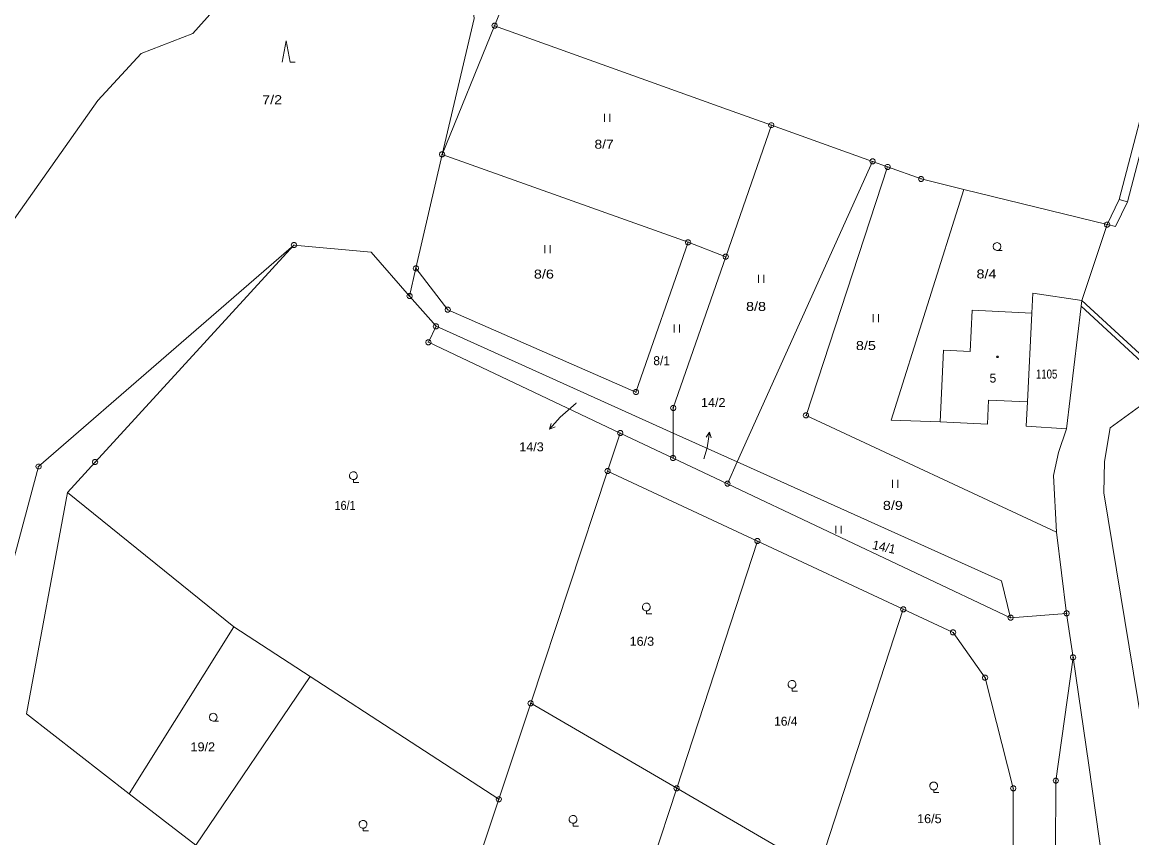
# Model space of a CAD drawing. Extents: x -687390 to -684106, y -954833 to -951648.
# Drawn here: x -686842.5 to -686632.4, y -952252.9 to -952098.4 of the extents above; entities that cross this region are included whole.
import ezdxf
from ezdxf.enums import TextEntityAlignment as Align

# ---------------------------------------------------------------- set-up
doc = ezdxf.new("R2010")
doc.units = 0
doc.header["$LTSCALE"] = 0.68
for name, color, linetype, lineweight in [('1', 7, 'Continuous', 13), ('3', 7, 'Continuous', 13), ('4', 7, 'Continuous', 13), ('5', 7, 'Continuous', 13), ('7', 7, 'Continuous', 13), ('8', 7, 'Continuous', 13)]:
    doc.layers.add(name, color=color, linetype=linetype, lineweight=lineweight)
doc.layers.add('2', color=7, linetype='Continuous')

msp = doc.modelspace()

# ---------------------------------------------------------------- linework, layer by layer
at = {"layer": '1'}
for p, q in [((-686753.07, -952099.08), (-686722.93, -952025.33)), ((-686624.07, -952090.85), (-686634.75, -952131.94)), ((-686753.07, -952099.08), (-686708.93, -952114.92)), ((-686678.63, -952125.8), (-686681.47, -952124.77)), ((-686678.63, -952125.8), (-686672.27, -952128.08)), ((-686672.27, -952128.08), (-686664.21, -952130.05)), ((-686664.21, -952130.05), (-686637.06, -952136.72)), ((-686637.06, -952136.72), (-686634.75, -952131.94)), ((-686641.87, -952151.11), (-686637.06, -952136.72)), ((-686791.07, -952140.62), (-686828.73, -952181.72)), ((-686767.96, -952145), (-686769.17, -952150.27)), ((-686769.17, -952150.27), (-686764.16, -952155.98)), ((-686662.64, -952152.96), (-686662.99, -952160.75)), ((-686651.34, -952153.47), (-686662.64, -952152.96)), ((-686651.34, -952153.47), (-686652.15, -952170.29)), ((-686729.26, -952176.22), (-686765.61, -952159.02)), ((-686668.65, -952174.1), (-686668.04, -952160.52)), ((-686662.99, -952160.75), (-686668.04, -952160.52)), ((-686659.51, -952169.96), (-686659.71, -952174.51)), ((-686652.15, -952170.29), (-686659.51, -952169.96)), ((-686652.15, -952170.29), (-686652.36, -952174.88)), ((-686659.71, -952174.51), (-686668.65, -952174.1)), ((-686644.75, -952175.43), (-686652.36, -952174.88)), ((-686719.24, -952176.21), (-686707.09, -952181.68)), ((-686833.98, -952187.46), (-686828.73, -952181.72)), ((-686657.05, -952204.22), (-686707.09, -952181.68)), ((-686647.2, -952184.25), (-686646.63, -952194.98)), ((-686841.73, -952229.38), (-686833.98, -952187.46)), ((-686703.29, -952196.66), (-686718.58, -952243.49)), ((-686646.63, -952194.98), (-686644.72, -952210.37)), ((-686675.65, -952209.59), (-686691.8, -952259.08)), ((-686655.32, -952211.18), (-686644.72, -952210.37)), ((-686644.72, -952210.37), (-686643.5, -952218.69)), ((-686643.5, -952218.69), (-686646.76, -952242.06)), ((-686643.5, -952218.69), (-686640.5, -952239.1)), ((-686752.26, -952245.56), (-686746.23, -952227.39)), ((-686635.56, -952274.27), (-686640.5, -952239.1)), ((-686718.58, -952243.49), (-686730.67, -952280.52))]:
    msp.add_line(p, q, dxfattribs=at)
for points in [[(-686704.5, -951972.19), (-686761.7, -952058.6), (-686756.92, -952097.72), (-686763.02, -952123.44)], [(-686798.99, -952084.75), (-686803.69, -952093.23), (-686810.2, -952100.56), (-686819.98, -952104.32), (-686828.22, -952113.25), (-686872.69, -952176.15), (-686879.03, -952189.6)], [(-686753.07, -952099.08), (-686763.02, -952123.44), (-686767.96, -952145)], [(-686681.47, -952124.77), (-686700.65, -952117.9), (-686708.93, -952114.92)], [(-686700.65, -952117.9), (-686709.29, -952142.81), (-686716.42, -952140.08), (-686763.02, -952123.44)], [(-686708.95, -952185.82), (-686707.09, -952181.68), (-686681.47, -952124.77)], [(-686678.63, -952125.8), (-686694.08, -952172.88), (-686646.63, -952194.98)], [(-686668.65, -952174.1), (-686677.96, -952173.76), (-686664.21, -952130.05)], [(-686791.07, -952140.62), (-686839.43, -952182.55), (-686849.46, -952219.82), (-686861.27, -952225.02), (-686852.17, -952273.36), (-686866.54, -952281.02)], [(-686769.17, -952150.27), (-686776.45, -952141.95), (-686791.07, -952140.62)], [(-686716.42, -952140.08), (-686726.3, -952168.45), (-686761.94, -952152.86), (-686767.96, -952145)], [(-686709.29, -952142.81), (-686719.22, -952171.46), (-686719.24, -952176.21), (-686719.25, -952180.95)], [(-686651.34, -952153.47), (-686651.09, -952149.69), (-686641.87, -952151.11), (-686641.99, -952152.16)], [(-686623.24, -952169.45), (-686641.99, -952152.16), (-686644.75, -952175.43)], [(-686765.61, -952159.02), (-686764.16, -952155.98), (-686719.24, -952176.21)], [(-686627.26, -952250.86), (-686637.68, -952187.53), (-686637.52, -952181.59), (-686636.46, -952175.22), (-686628.12, -952169.13), (-686623.24, -952169.45)], [(-686644.75, -952175.43), (-686646.26, -952179.91), (-686647.2, -952184.25)], [(-686746.23, -952227.39), (-686731.65, -952183.41), (-686729.26, -952176.22)], [(-686708.95, -952185.82), (-686719.25, -952180.95), (-686729.26, -952176.22)], [(-686731.65, -952183.41), (-686703.29, -952196.66), (-686675.65, -952209.59), (-686666.23, -952213.98), (-686660.17, -952222.54), (-686654.82, -952243.48), (-686654.84, -952268.78), (-686665.05, -952274.64), (-686691.8, -952259.08), (-686718.58, -952243.49), (-686746.23, -952227.39)], [(-686657.05, -952204.22), (-686655.32, -952211.18), (-686708.95, -952185.82)], [(-686841.73, -952229.38), (-686822.25, -952244.56), (-686802.48, -952212.91), (-686788.01, -952222.33)], [(-686822.25, -952244.56), (-686809.68, -952254.23), (-686788.01, -952222.33)], [(-686757.85, -952262.42), (-686752.26, -952245.56), (-686788.01, -952222.33)], [(-686646.76, -952242.06), (-686646.86, -952269.57), (-686655.44, -952300.69)]]:
    msp.add_lwpolyline(points, dxfattribs=at)
at = {"layer": '3'}
for p, q in [((-686732.26, -952115.74), (-686732.26, -952117.24)), ((-686731.26, -952117.24), (-686731.26, -952115.74)), ((-686743.57, -952140.61), (-686743.57, -952142.11)), ((-686742.57, -952142.11), (-686742.57, -952140.61)), ((-686703.05, -952146.26), (-686703.05, -952147.76)), ((-686702.05, -952147.76), (-686702.05, -952146.26)), ((-686681.35, -952153.7), (-686681.35, -952155.2)), ((-686680.35, -952155.2), (-686680.35, -952153.7)), ((-686719.03, -952155.67), (-686719.03, -952157.17)), ((-686718.03, -952157.17), (-686718.03, -952155.67)), ((-686677.69, -952185.07), (-686677.69, -952186.57)), ((-686676.69, -952186.57), (-686676.69, -952185.07)), ((-686688.43, -952193.75), (-686688.43, -952195.25)), ((-686687.43, -952195.25), (-686687.43, -952193.75))]:
    msp.add_line(p, q, dxfattribs=at)
for points in [[(-686793.31, -952105.93), (-686792.56, -952101.93), (-686791.81, -952105.93), (-686790.81, -952105.93)], [(-686657.89, -952141.62), (-686658.27, -952141.52), (-686658.54, -952141.25), (-686658.64, -952140.88), (-686658.54, -952140.51), (-686658.27, -952140.24), (-686657.9, -952140.14), (-686657.53, -952140.24), (-686657.26, -952140.51), (-686657.16, -952140.89), (-686657.26, -952141.27), (-686657.53, -952141.54), (-686657.91, -952141.64), (-686656.91, -952141.64)], [(-686779.81, -952185.01), (-686780, -952185.01), (-686780.34, -952184.82), (-686780.53, -952184.48), (-686780.53, -952184.09), (-686780.34, -952183.75), (-686780, -952183.56), (-686779.61, -952183.56), (-686779.27, -952183.75), (-686779.08, -952184.09), (-686779.08, -952184.48), (-686779.27, -952184.82), (-686779.61, -952185.01), (-686779.8, -952185.01), (-686779.8, -952185.54), (-686778.8, -952185.54)], [(-686724.32, -952209.9), (-686724.51, -952209.9), (-686724.85, -952209.71), (-686725.04, -952209.37), (-686725.04, -952208.98), (-686724.85, -952208.64), (-686724.51, -952208.45), (-686724.12, -952208.45), (-686723.78, -952208.64), (-686723.59, -952208.98), (-686723.59, -952209.37), (-686723.78, -952209.71), (-686724.12, -952209.9), (-686724.31, -952209.9), (-686724.31, -952210.43), (-686723.31, -952210.43)], [(-686696.72, -952224.55), (-686696.91, -952224.55), (-686697.25, -952224.36), (-686697.44, -952224.02), (-686697.44, -952223.63), (-686697.25, -952223.29), (-686696.91, -952223.1), (-686696.52, -952223.1), (-686696.18, -952223.29), (-686695.99, -952223.63), (-686695.99, -952224.02), (-686696.18, -952224.36), (-686696.52, -952224.55), (-686696.71, -952224.55), (-686696.71, -952225.08), (-686695.71, -952225.08)], [(-686806.34, -952230.76), (-686806.72, -952230.66), (-686806.99, -952230.39), (-686807.09, -952230.02), (-686806.99, -952229.65), (-686806.72, -952229.38), (-686806.35, -952229.28), (-686805.98, -952229.38), (-686805.71, -952229.65), (-686805.61, -952230.03), (-686805.71, -952230.41), (-686805.98, -952230.68), (-686806.36, -952230.78), (-686805.36, -952230.78)], [(-686669.91, -952243.76), (-686670.1, -952243.76), (-686670.44, -952243.57), (-686670.63, -952243.23), (-686670.63, -952242.84), (-686670.44, -952242.5), (-686670.1, -952242.31), (-686669.71, -952242.31), (-686669.37, -952242.5), (-686669.18, -952242.84), (-686669.18, -952243.23), (-686669.37, -952243.57), (-686669.71, -952243.76), (-686669.9, -952243.76), (-686669.9, -952244.29), (-686668.9, -952244.29)], [(-686738.2, -952250.1), (-686738.39, -952250.1), (-686738.73, -952249.91), (-686738.92, -952249.57), (-686738.92, -952249.18), (-686738.73, -952248.84), (-686738.39, -952248.65), (-686738, -952248.65), (-686737.66, -952248.84), (-686737.47, -952249.18), (-686737.47, -952249.57), (-686737.66, -952249.91), (-686738, -952250.1), (-686738.19, -952250.1), (-686738.19, -952250.63), (-686737.19, -952250.63)], [(-686777.98, -952251.01), (-686778.17, -952251.01), (-686778.51, -952250.82), (-686778.7, -952250.48), (-686778.7, -952250.09), (-686778.51, -952249.75), (-686778.17, -952249.56), (-686777.78, -952249.56), (-686777.44, -952249.75), (-686777.25, -952250.09), (-686777.25, -952250.48), (-686777.44, -952250.82), (-686777.78, -952251.01), (-686777.97, -952251.01), (-686777.97, -952251.54), (-686776.97, -952251.54)]]:
    msp.add_lwpolyline(points, dxfattribs=at)
at = {"layer": '4'}
for p, q in [((-686635.49, -952137.11), (-686633.22, -952132.4)), ((-686635.49, -952137.11), (-686637.06, -952136.72)), ((-686641.87, -952151.11), (-686608.66, -952181.61)), ((-686833.98, -952187.46), (-686802.48, -952212.91))]:
    msp.add_line(p, q, dxfattribs=at)
msp.add_lwpolyline([(-686634.75, -952131.94), (-686633.22, -952132.4), (-686602.22, -952013.72)], dxfattribs=at)
at = {"layer": '5'}
msp.add_lwpolyline([(-686657.72, -952161.62), (-686657.63, -952161.77), (-686657.72, -952161.92), (-686657.9, -952161.92), (-686657.99, -952161.77), (-686657.9, -952161.62)], close=True, dxfattribs=at)
at = {"layer": '7'}
for p, q in [((-686737.6, -952170.56), (-686740.67, -952173.2)), ((-686742.647, -952175.456), (-686740.67, -952173.2)), ((-686712.373, -952176.062), (-686712.81, -952179.03)), ((-686713.43, -952181.1), (-686712.81, -952179.03))]:
    msp.add_line(p, q, dxfattribs=at)
for points in [[(-686741.612, -952175.034), (-686742.647, -952175.456), (-686742.364, -952174.375)], [(-686713.013, -952176.978), (-686712.373, -952176.062), (-686712.024, -952177.124)]]:
    msp.add_lwpolyline(points, dxfattribs=at)
at = {"layer": '8'}
for p, q in [((-686753.19, -952099.08), (-686752.95, -952099.08)), ((-686700.77, -952117.9), (-686700.53, -952117.9)), ((-686763.14, -952123.44), (-686762.9, -952123.44)), ((-686681.59, -952124.77), (-686681.35, -952124.77)), ((-686678.75, -952125.8), (-686678.51, -952125.8)), ((-686672.39, -952128.08), (-686672.15, -952128.08)), ((-686637.18, -952136.72), (-686636.94, -952136.72)), ((-686791.19, -952140.62), (-686790.95, -952140.62)), ((-686716.54, -952140.08), (-686716.3, -952140.08)), ((-686709.41, -952142.81), (-686709.17, -952142.81)), ((-686768.08, -952145), (-686767.84, -952145)), ((-686769.29, -952150.27), (-686769.05, -952150.27)), ((-686762.06, -952152.86), (-686761.82, -952152.86)), ((-686764.28, -952155.98), (-686764.04, -952155.98)), ((-686765.73, -952159.02), (-686765.49, -952159.02)), ((-686726.42, -952168.45), (-686726.18, -952168.45)), ((-686719.34, -952171.46), (-686719.1, -952171.46)), ((-686694.2, -952172.88), (-686693.96, -952172.88)), ((-686729.38, -952176.22), (-686729.14, -952176.22)), ((-686828.85, -952181.72), (-686828.61, -952181.72)), ((-686719.37, -952180.95), (-686719.13, -952180.95)), ((-686839.55, -952182.55), (-686839.31, -952182.55)), ((-686731.77, -952183.41), (-686731.53, -952183.41)), ((-686709.07, -952185.82), (-686708.83, -952185.82)), ((-686703.41, -952196.66), (-686703.17, -952196.66)), ((-686675.77, -952209.59), (-686675.53, -952209.59)), ((-686655.44, -952211.18), (-686655.2, -952211.18)), ((-686644.84, -952210.37), (-686644.6, -952210.37)), ((-686666.35, -952213.98), (-686666.11, -952213.98)), ((-686643.62, -952218.69), (-686643.38, -952218.69)), ((-686660.29, -952222.54), (-686660.05, -952222.54)), ((-686746.35, -952227.39), (-686746.11, -952227.39)), ((-686646.88, -952242.06), (-686646.64, -952242.06)), ((-686718.7, -952243.49), (-686718.46, -952243.49)), ((-686654.94, -952243.48), (-686654.7, -952243.48)), ((-686752.38, -952245.56), (-686752.14, -952245.56))]:
    msp.add_line(p, q, dxfattribs=at)
for points in [[(-686752.92, -952098.6), (-686752.67, -952098.78), (-686752.57, -952099.07), (-686752.67, -952099.36), (-686752.92, -952099.54), (-686753.23, -952099.54), (-686753.48, -952099.36), (-686753.58, -952099.07), (-686753.48, -952098.78), (-686753.23, -952098.6)], [(-686700.5, -952117.42), (-686700.25, -952117.6), (-686700.15, -952117.89), (-686700.25, -952118.18), (-686700.5, -952118.36), (-686700.81, -952118.36), (-686701.06, -952118.18), (-686701.16, -952117.89), (-686701.06, -952117.6), (-686700.81, -952117.42)], [(-686762.87, -952122.96), (-686762.62, -952123.14), (-686762.52, -952123.43), (-686762.62, -952123.72), (-686762.87, -952123.9), (-686763.18, -952123.9), (-686763.43, -952123.72), (-686763.53, -952123.43), (-686763.43, -952123.14), (-686763.18, -952122.96)], [(-686681.32, -952124.29), (-686681.07, -952124.47), (-686680.97, -952124.76), (-686681.07, -952125.05), (-686681.32, -952125.23), (-686681.63, -952125.23), (-686681.88, -952125.05), (-686681.98, -952124.76), (-686681.88, -952124.47), (-686681.63, -952124.29)], [(-686678.48, -952125.32), (-686678.23, -952125.5), (-686678.13, -952125.79), (-686678.23, -952126.08), (-686678.48, -952126.26), (-686678.79, -952126.26), (-686679.04, -952126.08), (-686679.14, -952125.79), (-686679.04, -952125.5), (-686678.79, -952125.32)], [(-686672.12, -952127.6), (-686671.87, -952127.78), (-686671.77, -952128.07), (-686671.87, -952128.36), (-686672.12, -952128.54), (-686672.43, -952128.54), (-686672.68, -952128.36), (-686672.78, -952128.07), (-686672.68, -952127.78), (-686672.43, -952127.6)], [(-686636.91, -952136.24), (-686636.66, -952136.42), (-686636.56, -952136.71), (-686636.66, -952137), (-686636.91, -952137.18), (-686637.22, -952137.18), (-686637.47, -952137), (-686637.57, -952136.71), (-686637.47, -952136.42), (-686637.22, -952136.24)], [(-686716.27, -952139.6), (-686716.02, -952139.78), (-686715.92, -952140.07), (-686716.02, -952140.36), (-686716.27, -952140.54), (-686716.58, -952140.54), (-686716.83, -952140.36), (-686716.93, -952140.07), (-686716.83, -952139.78), (-686716.58, -952139.6)], [(-686790.92, -952140.14), (-686790.67, -952140.32), (-686790.57, -952140.61), (-686790.67, -952140.9), (-686790.92, -952141.08), (-686791.23, -952141.08), (-686791.48, -952140.9), (-686791.58, -952140.61), (-686791.48, -952140.32), (-686791.23, -952140.14)], [(-686709.14, -952142.33), (-686708.89, -952142.51), (-686708.79, -952142.8), (-686708.89, -952143.09), (-686709.14, -952143.27), (-686709.45, -952143.27), (-686709.7, -952143.09), (-686709.8, -952142.8), (-686709.7, -952142.51), (-686709.45, -952142.33)], [(-686767.81, -952144.52), (-686767.56, -952144.7), (-686767.46, -952144.99), (-686767.56, -952145.28), (-686767.81, -952145.46), (-686768.12, -952145.46), (-686768.37, -952145.28), (-686768.47, -952144.99), (-686768.37, -952144.7), (-686768.12, -952144.52)], [(-686769.02, -952149.79), (-686768.77, -952149.97), (-686768.67, -952150.26), (-686768.77, -952150.55), (-686769.02, -952150.73), (-686769.33, -952150.73), (-686769.58, -952150.55), (-686769.68, -952150.26), (-686769.58, -952149.97), (-686769.33, -952149.79)], [(-686761.79, -952152.38), (-686761.54, -952152.56), (-686761.44, -952152.85), (-686761.54, -952153.14), (-686761.79, -952153.32), (-686762.1, -952153.32), (-686762.35, -952153.14), (-686762.45, -952152.85), (-686762.35, -952152.56), (-686762.1, -952152.38)], [(-686764.01, -952155.5), (-686763.76, -952155.68), (-686763.66, -952155.97), (-686763.76, -952156.26), (-686764.01, -952156.44), (-686764.32, -952156.44), (-686764.57, -952156.26), (-686764.67, -952155.97), (-686764.57, -952155.68), (-686764.32, -952155.5)], [(-686765.46, -952158.54), (-686765.21, -952158.72), (-686765.11, -952159.01), (-686765.21, -952159.3), (-686765.46, -952159.48), (-686765.77, -952159.48), (-686766.02, -952159.3), (-686766.12, -952159.01), (-686766.02, -952158.72), (-686765.77, -952158.54)], [(-686726.15, -952167.97), (-686725.9, -952168.15), (-686725.8, -952168.44), (-686725.9, -952168.73), (-686726.15, -952168.91), (-686726.46, -952168.91), (-686726.71, -952168.73), (-686726.81, -952168.44), (-686726.71, -952168.15), (-686726.46, -952167.97)], [(-686719.07, -952170.98), (-686718.82, -952171.16), (-686718.72, -952171.45), (-686718.82, -952171.74), (-686719.07, -952171.92), (-686719.38, -952171.92), (-686719.63, -952171.74), (-686719.73, -952171.45), (-686719.63, -952171.16), (-686719.38, -952170.98)], [(-686693.93, -952172.4), (-686693.68, -952172.58), (-686693.58, -952172.87), (-686693.68, -952173.16), (-686693.93, -952173.34), (-686694.24, -952173.34), (-686694.49, -952173.16), (-686694.59, -952172.87), (-686694.49, -952172.58), (-686694.24, -952172.4)], [(-686729.11, -952175.74), (-686728.86, -952175.92), (-686728.76, -952176.21), (-686728.86, -952176.5), (-686729.11, -952176.68), (-686729.42, -952176.68), (-686729.67, -952176.5), (-686729.77, -952176.21), (-686729.67, -952175.92), (-686729.42, -952175.74)], [(-686828.58, -952181.24), (-686828.33, -952181.42), (-686828.23, -952181.71), (-686828.33, -952182), (-686828.58, -952182.18), (-686828.89, -952182.18), (-686829.14, -952182), (-686829.24, -952181.71), (-686829.14, -952181.42), (-686828.89, -952181.24)], [(-686719.1, -952180.47), (-686718.85, -952180.65), (-686718.75, -952180.94), (-686718.85, -952181.23), (-686719.1, -952181.41), (-686719.41, -952181.41), (-686719.66, -952181.23), (-686719.76, -952180.94), (-686719.66, -952180.65), (-686719.41, -952180.47)], [(-686839.28, -952182.07), (-686839.03, -952182.25), (-686838.93, -952182.54), (-686839.03, -952182.83), (-686839.28, -952183.01), (-686839.59, -952183.01), (-686839.84, -952182.83), (-686839.94, -952182.54), (-686839.84, -952182.25), (-686839.59, -952182.07)], [(-686731.5, -952182.93), (-686731.25, -952183.11), (-686731.15, -952183.4), (-686731.25, -952183.69), (-686731.5, -952183.87), (-686731.81, -952183.87), (-686732.06, -952183.69), (-686732.16, -952183.4), (-686732.06, -952183.11), (-686731.81, -952182.93)], [(-686708.8, -952185.34), (-686708.55, -952185.52), (-686708.45, -952185.81), (-686708.55, -952186.1), (-686708.8, -952186.28), (-686709.11, -952186.28), (-686709.36, -952186.1), (-686709.46, -952185.81), (-686709.36, -952185.52), (-686709.11, -952185.34)], [(-686703.14, -952196.18), (-686702.89, -952196.36), (-686702.79, -952196.65), (-686702.89, -952196.94), (-686703.14, -952197.12), (-686703.45, -952197.12), (-686703.7, -952196.94), (-686703.8, -952196.65), (-686703.7, -952196.36), (-686703.45, -952196.18)], [(-686675.5, -952209.11), (-686675.25, -952209.29), (-686675.15, -952209.58), (-686675.25, -952209.87), (-686675.5, -952210.05), (-686675.81, -952210.05), (-686676.06, -952209.87), (-686676.16, -952209.58), (-686676.06, -952209.29), (-686675.81, -952209.11)], [(-686655.17, -952210.7), (-686654.92, -952210.88), (-686654.82, -952211.17), (-686654.92, -952211.46), (-686655.17, -952211.64), (-686655.48, -952211.64), (-686655.73, -952211.46), (-686655.83, -952211.17), (-686655.73, -952210.88), (-686655.48, -952210.7)], [(-686644.57, -952209.89), (-686644.32, -952210.07), (-686644.22, -952210.36), (-686644.32, -952210.65), (-686644.57, -952210.83), (-686644.88, -952210.83), (-686645.13, -952210.65), (-686645.23, -952210.36), (-686645.13, -952210.07), (-686644.88, -952209.89)], [(-686666.08, -952213.5), (-686665.83, -952213.68), (-686665.73, -952213.97), (-686665.83, -952214.26), (-686666.08, -952214.44), (-686666.39, -952214.44), (-686666.64, -952214.26), (-686666.74, -952213.97), (-686666.64, -952213.68), (-686666.39, -952213.5)], [(-686643.35, -952218.21), (-686643.1, -952218.39), (-686643, -952218.68), (-686643.1, -952218.97), (-686643.35, -952219.15), (-686643.66, -952219.15), (-686643.91, -952218.97), (-686644.01, -952218.68), (-686643.91, -952218.39), (-686643.66, -952218.21)], [(-686660.02, -952222.06), (-686659.77, -952222.24), (-686659.67, -952222.53), (-686659.77, -952222.82), (-686660.02, -952223), (-686660.33, -952223), (-686660.58, -952222.82), (-686660.68, -952222.53), (-686660.58, -952222.24), (-686660.33, -952222.06)], [(-686746.08, -952226.91), (-686745.83, -952227.09), (-686745.73, -952227.38), (-686745.83, -952227.67), (-686746.08, -952227.85), (-686746.39, -952227.85), (-686746.64, -952227.67), (-686746.74, -952227.38), (-686746.64, -952227.09), (-686746.39, -952226.91)], [(-686646.61, -952241.58), (-686646.36, -952241.76), (-686646.26, -952242.05), (-686646.36, -952242.34), (-686646.61, -952242.52), (-686646.92, -952242.52), (-686647.17, -952242.34), (-686647.27, -952242.05), (-686647.17, -952241.76), (-686646.92, -952241.58)], [(-686718.43, -952243.01), (-686718.18, -952243.19), (-686718.08, -952243.48), (-686718.18, -952243.77), (-686718.43, -952243.95), (-686718.74, -952243.95), (-686718.99, -952243.77), (-686719.09, -952243.48), (-686718.99, -952243.19), (-686718.74, -952243.01)], [(-686654.67, -952243), (-686654.42, -952243.18), (-686654.32, -952243.47), (-686654.42, -952243.76), (-686654.67, -952243.94), (-686654.98, -952243.94), (-686655.23, -952243.76), (-686655.33, -952243.47), (-686655.23, -952243.18), (-686654.98, -952243)], [(-686752.11, -952245.08), (-686751.86, -952245.26), (-686751.76, -952245.55), (-686751.86, -952245.84), (-686752.11, -952246.02), (-686752.42, -952246.02), (-686752.67, -952245.84), (-686752.77, -952245.55), (-686752.67, -952245.26), (-686752.42, -952245.08)]]:
    msp.add_lwpolyline(points, close=True, dxfattribs=at)

# ---------------------------------------------------------------- texts
at = {"layer": '2'}
for s, width, p in [('7/2', 1.2, (-686797.095, -952113.92)), ('8/4', 1.2, (-686661.795, -952146.92)), ('8/5', 1.2, (-686684.635, -952160.48)), ('1105', 0.8, (-686650.535, -952165.88)), ('16/1', 0.9, (-686783.375, -952190.75)), ('19/2', 1.05, (-686810.655, -952236.49))]:
    msp.add_text(s, height=1.7, dxfattribs=dict(at, width=width)).set_placement(p)
for s, height, width, p in [('8/7', 1.7, 1.15, (-686732.33, -952122.35)), ('8/6', 1.7, 1.2, (-686743.73, -952146.95)), ('8/8', 1.7, 1.2, (-686703.55, -952153.08)), ('14/3', 0.1, 1.05, (-686737.6, -952170.56)), ('14/2', 0.1, 1.05, (-686713.43, -952181.1)), ('8/9', 1.7, 1.2, (-686677.63, -952190.76)), ('16/3', 1.7, 1.05, (-686725.17, -952216.49)), ('16/5', 1.7, 1.05, (-686670.72, -952250.09))]:
    msp.add_text(s, height=height, dxfattribs=dict(at, width=width)).set_placement(p, align=Align.CENTER)
for s, p in [('8/1', (-686723.005, -952163.35)), ('5', (-686659.315, -952166.65))]:
    msp.add_text(s, height=1.7, dxfattribs=at).set_placement(p)
msp.add_text('14/1', height=1.7, rotation=347.499, dxfattribs=at).set_placement((-686679.476, -952198.621), align=Align.CENTER)
msp.add_text('16/4', height=1.7, dxfattribs=at).set_placement((-686697.91, -952231.63), align=Align.CENTER)
at = {"layer": '7', "width": 1.05}
msp.add_text('14/2', height=1.7, dxfattribs=at).set_placement((-686713.975, -952171.27))
msp.add_text('14/3', height=1.7, dxfattribs=at).set_placement((-686743.756, -952179.67), align=Align.RIGHT)

doc.saveas('drawing.dxf')
